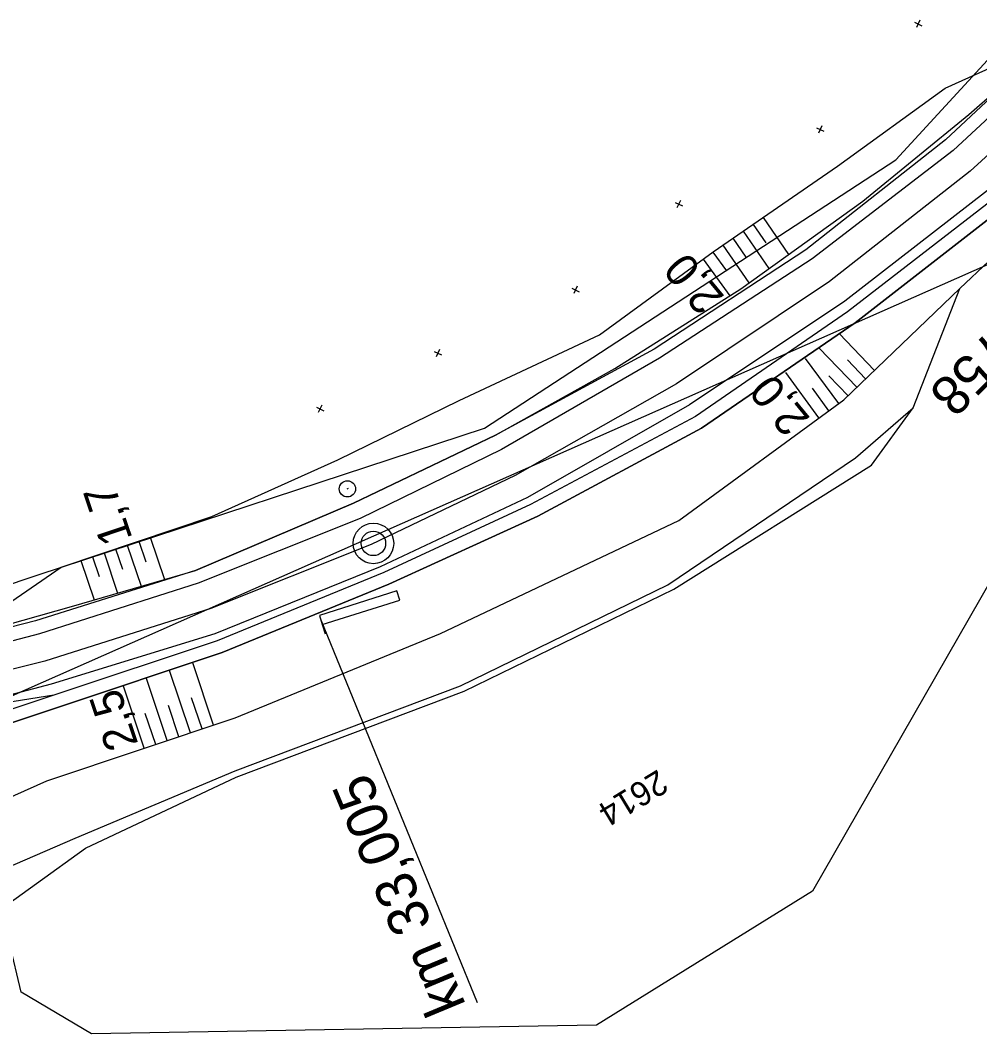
# Model space of a CAD drawing. Extents: x -804166 to -803706, y -1151030 to -1150147.
# Drawn here: x -803968.4 to -803909.4, y -1150743 to -1150680.7 of the extents above; entities that cross this region are included whole.
import ezdxf

# ---------------------------------------------------------------- set-up
doc = ezdxf.new("R2010")
doc.units = 0
for name, color, linetype in [('0381KM032-037P - Vrstva 1', 7, 'Continuous'), ('0381KM032-037P - Vrstva 13', 7, 'Continuous'), ('0381KM032-037P - Vrstva 4', 7, 'Continuous'), ('0381KM032-037P - Vrstva 48', 7, 'Continuous'), ('0381KM032-037P - Vrstva 49', 7, 'Continuous'), ('0381KM032-037P - Vrstva 57', 7, 'Continuous'), ('0381KM032-037P - Vrstva 7', 7, 'Continuous'), ('0381KM032-037P - Vrstva 9', 7, 'Continuous'), ('hran DP - hran DP', 7, 'Continuous'), ('vyt_sit - polygon', 7, 'Continuous'), ('vyt_sit - stávající', 7, 'Continuous')]:
    doc.layers.add(name, color=color, linetype=linetype)

msp = doc.modelspace()

# ---------------------------------------------------------------- linework, layer by layer
at = {"layer": '0381KM032-037P - Vrstva 1'}
msp.add_lwpolyline([(-803901.906, -1150682.605), (-803910.014, -1150690), (-803918.643, -1150696.775), (-803928.041, -1150703.062), (-803937.946, -1150708.688), (-803946.795, -1150712.932), (-803956.655, -1150716.869), (-803966.853, -1150720.098), (-803973.694, -1150721.813), (-803983.505, -1150723.682), (-803993.918, -1150724.91), (-804004.459, -1150725.421), (-804014.948, -1150725.206), (-804025.475, -1150724.252), (-804035.41, -1150722.673), (-804044.081, -1150720.735), (-804054.774, -1150717.615), (-804061.472, -1150715.138)], dxfattribs=at)
at = {"layer": '0381KM032-037P - Vrstva 13'}
for points in [[(-803902.54, -1150686.99), (-803908.533, -1150691.682), (-803917.537, -1150698.646), (-803926.885, -1150705.063), (-803937.003, -1150710.487), (-803946.017, -1150714.661), (-803956.263, -1150718.85), (-803966.288, -1150722.189), (-803972.538, -1150724.259)], [(-803972.286, -1150725.012), (-803966.125, -1150722.974), (-803955.955, -1150719.581), (-803945.709, -1150715.376), (-803936.565, -1150711.19), (-803926.506, -1150705.78), (-803917.073, -1150699.315), (-803908.044, -1150692.29), (-803902.092, -1150687.65)]]:
    msp.add_lwpolyline(points, dxfattribs=at)
at = {"layer": '0381KM032-037P - Vrstva 4'}
msp.add_line((-803966.288, -1150722.189), (-803973.383, -1150723.337), dxfattribs=at)
for points in [[(-803904.886, -1150683.001), (-803906.516, -1150683.391), (-803911.518, -1150688.069), (-803920.109, -1150694.835), (-803929.412, -1150700.935), (-803939.155, -1150706.209), (-803947.889, -1150710.398), (-803957.601, -1150714.533), (-803967.413, -1150717.637)], [(-803904.886, -1150683.001), (-803911.05, -1150688.735), (-803919.705, -1150695.384), (-803929.087, -1150701.477), (-803938.787, -1150707.105), (-803947.481, -1150711.337), (-803957.418, -1150715.321), (-803967.176, -1150718.433)], [(-803902.503, -1150685.469), (-803908.943, -1150691.185), (-803917.694, -1150697.991), (-803927.241, -1150704.348), (-803937.195, -1150710.055), (-803946.246, -1150714.302), (-803956.405, -1150718.419), (-803966.448, -1150721.526)], [(-803902.503, -1150685.469), (-803902.54, -1150686.99), (-803908.533, -1150691.682), (-803917.537, -1150698.646), (-803926.885, -1150705.063), (-803937.003, -1150710.487), (-803946.017, -1150714.661), (-803956.263, -1150718.85), (-803966.288, -1150722.189)], [(-803967.413, -1150717.637), (-803975.823, -1150719.769), (-803983.88, -1150721.36), (-803994.176, -1150722.403), (-804004.636, -1150722.95), (-804014.864, -1150722.688), (-804025.142, -1150721.989), (-804034.984, -1150720.624), (-804043.408, -1150718.773), (-804051.925, -1150716.215), (-804054.245, -1150715.484), (-804061.999, -1150712.588)], [(-803967.176, -1150718.433), (-803974.218, -1150720.269), (-803983.735, -1150722.132), (-803994.129, -1150723.262), (-804004.519, -1150723.869), (-804015.047, -1150723.539), (-804025.265, -1150722.781), (-804035.168, -1150721.131), (-804043.667, -1150719.322), (-804054.385, -1150716.187), (-804061.833, -1150713.392)], [(-803966.448, -1150721.526), (-803973.383, -1150723.337), (-803975.353, -1150723.792), (-803983.323, -1150725.373), (-803993.816, -1150726.434), (-804004.802, -1150726.955), (-804015.292, -1150726.922), (-804025.602, -1150725.763), (-804035.878, -1150724.109), (-804044.498, -1150722.129), (-804055.401, -1150719.075), (-804061.092, -1150716.98)]]:
    msp.add_lwpolyline(points, dxfattribs=at)
at = {"layer": '0381KM032-037P - Vrstva 48'}
for p, q in [((-803922.724, -1150692.839), (-803921.156, -1150695.111)), ((-803923.341, -1150693.265), (-803922.553, -1150694.407)), ((-803924.575, -1150694.118), (-803923.779, -1150695.271)), ((-803923.958, -1150693.691), (-803922.374, -1150695.987)), ((-803925.193, -1150694.544), (-803923.592, -1150696.863)), ((-803925.809, -1150694.97), (-803924.975, -1150696.112)), ((-803926.415, -1150695.413), (-803924.777, -1150697.655)), ((-803915.883, -1150702.24), (-803918.059, -1150699.974)), ((-803916.965, -1150703.279), (-803919.272, -1150700.876)), ((-803918.079, -1150704.279), (-803920.11, -1150701.499)), ((-803916.424, -1150702.759), (-803917.545, -1150701.592)), ((-803919.291, -1150705.163), (-803921.33, -1150702.372)), ((-803917.506, -1150703.798), (-803918.692, -1150702.563)), ((-803918.685, -1150704.721), (-803919.698, -1150703.334)), ((-803961.077, -1150712.73), (-803960.645, -1150714.011)), ((-803960.366, -1150712.49), (-803959.492, -1150715.083)), ((-803962.498, -1150713.21), (-803962.076, -1150714.461)), ((-803961.787, -1150712.97), (-803960.933, -1150715.502)), ((-803964.63, -1150713.929), (-803963.816, -1150716.341)), ((-803963.919, -1150713.689), (-803963.508, -1150714.91)), ((-803963.209, -1150713.449), (-803962.375, -1150715.921)), ((-803956.479, -1150724.031), (-803957.763, -1150720.201)), ((-803957.902, -1150724.508), (-803959.183, -1150720.684)), ((-803959.324, -1150724.985), (-803960.603, -1150721.167)), ((-803960.746, -1150725.461), (-803962.023, -1150721.65)), ((-803957.19, -1150724.27), (-803957.832, -1150722.356)), ((-803960.035, -1150725.223), (-803960.674, -1150723.316)), ((-803958.613, -1150724.746), (-803959.253, -1150722.836))]:
    msp.add_line(p, q, dxfattribs=at)
at = {"layer": '0381KM032-037P - Vrstva 49'}
for p, q in [((-803913.423, -1150680.841), (-803912.971, -1150681.057)), ((-803913.089, -1150680.723), (-803913.305, -1150681.175)), ((-803919.115, -1150687.214), (-803919.331, -1150687.666)), ((-803919.449, -1150687.332), (-803918.997, -1150687.548)), ((-803928.133, -1150691.918), (-803927.681, -1150692.134)), ((-803927.799, -1150691.8), (-803928.015, -1150692.252)), ((-803934.479, -1150697.185), (-803934.027, -1150697.401)), ((-803934.145, -1150697.067), (-803934.361, -1150697.519)), ((-803942.593, -1150700.952), (-803942.809, -1150701.404)), ((-803942.927, -1150701.07), (-803942.475, -1150701.286)), ((-803950.166, -1150704.501), (-803949.714, -1150704.717)), ((-803949.832, -1150704.383), (-803950.048, -1150704.835))]:
    msp.add_line(p, q, dxfattribs=at)
for points in [[(-803984.817, -1150721.442), (-803974.636, -1150719.233), (-803973.09, -1150718.927), (-803972.805, -1150718.807), (-803972.246, -1150718.741), (-803965.21, -1150716.746), (-803957.601, -1150714.533), (-803947.889, -1150710.398), (-803939.155, -1150706.209), (-803931.831, -1150702.119), (-803924.086, -1150697.218), (-803916.608, -1150691.841), (-803910.081, -1150686.51), (-803906.516, -1150683.391), (-803903.605, -1150681.318)], [(-803972.246, -1150718.741), (-803965.841, -1150714.337), (-803956.596, -1150711.219), (-803948.841, -1150707.727), (-803941.393, -1150704.085), (-803932.776, -1150700.061), (-803925.787, -1150694.954), (-803918.146, -1150689.679), (-803911.549, -1150684.903), (-803903.605, -1150681.318)], [(-803973.24, -1150730.36), (-803966.718, -1150727.463), (-803955.163, -1150723.59), (-803942.536, -1150718.416), (-803927.909, -1150711.458), (-803917.773, -1150704.055), (-803910.649, -1150697.212), (-803903.52, -1150690.487), (-803900.099, -1150686.57)], [(-803902.092, -1150687.65), (-803908.044, -1150692.29), (-803917.073, -1150699.315), (-803926.506, -1150705.78), (-803936.565, -1150711.19), (-803945.709, -1150715.376), (-803955.955, -1150719.581), (-803966.125, -1150722.974), (-803972.286, -1150725.012), (-803974.7, -1150725.768), (-803983.368, -1150727.37), (-803993.836, -1150727.905), (-804004.989, -1150728.615), (-804004.868, -1150729.928), (-804012.985, -1150730.258), (-804018.762, -1150729.808), (-804029.792, -1150728.642), (-804054.152, -1150723.147), (-804060.274, -1150720.943)], [(-803970.39, -1150735.93), (-803964.347, -1150731.606), (-803955.102, -1150727.225), (-803941.078, -1150721.948), (-803928.207, -1150715.68), (-803916.068, -1150708.06), (-803913.504, -1150704.534), (-803910.649, -1150697.212)], [(-803971.76, -1150733.922), (-803964.987, -1150730.973), (-803955.152, -1150726.847), (-803941.304, -1150721.616), (-803928.584, -1150715.413), (-803917.051, -1150707.621), (-803913.504, -1150704.534)]]:
    msp.add_lwpolyline(points, dxfattribs=at)
at = {"layer": '0381KM032-037P - Vrstva 7'}
msp.add_line((-803948.213, -1150709.499), (-803948.305, -1150709.537), dxfattribs=at)
for centre, radius in [((-803948.259, -1150709.518), 0.5), ((-803946.663, -1150712.869), 1.246), ((-803946.663, -1150712.869), 0.752)]:
    msp.add_circle(centre, radius, dxfattribs=at)
at = {"layer": '0381KM032-037P - Vrstva 9'}
for p, q in [((-803945.217, -1150715.777), (-803949.983, -1150717.29)), ((-803945.036, -1150716.348), (-803945.217, -1150715.777)), ((-803949.801, -1150717.862), (-803945.036, -1150716.348)), ((-803949.983, -1150717.29), (-803949.801, -1150717.862)), ((-803949.892, -1150717.576), (-803940.281, -1150741.083)), ((-803949.801, -1150717.862), (-803949.62, -1150718.434))]:
    msp.add_line(p, q, dxfattribs=at)
at = {"layer": 'hran DP - hran DP'}
for p, q in [((-803914.58, -1150689.29), (-803907.67, -1150681.78)), ((-803939.84, -1150705.78), (-803914.58, -1150689.29)), ((-803967.26, -1150714.81), (-803939.84, -1150705.78)), ((-803905.7, -1150709.82), (-803919.68, -1150734.23)), ((-803976.9, -1150717.98), (-803967.26, -1150714.81)), ((-803968.3, -1150740.45), (-803970.22, -1150732.49)), ((-803919.68, -1150734.23), (-803932.96, -1150742.47)), ((-803963.98, -1150743), (-803968.3, -1150740.45)), ((-803932.96, -1150742.47), (-803963.98, -1150743))]:
    msp.add_line(p, q, dxfattribs=at)
at = {"layer": 'vyt_sit - polygon'}
msp.add_line((-803975.818, -1150725.31), (-803907.43, -1150695.075), dxfattribs=at)

# ---------------------------------------------------------------- texts
at = {"layer": '0381KM032-037P - Vrstva 48'}
for s, rotation, p in [('2,0', 129.61944, (-803925.039, -1150697.72)), ('2,0', 129.42518, (-803919.779, -1150705.196)), ('1,7', 108.63737, (-803961.445, -1150712.571)), ('2,5', 108.45016, (-803961.097, -1150725.192))]:
    msp.add_text(s, height=2, rotation=rotation, dxfattribs=at).set_placement(p)
at = {"layer": '0381KM032-037P - Vrstva 57'}
msp.add_text('2614', height=1.5, rotation=211.19956, dxfattribs=at).set_placement((-803929.177, -1150726.725))
at = {"layer": '0381KM032-037P - Vrstva 9'}
msp.add_text('km 33,005', height=2.5, rotation=112.61933, dxfattribs=at).set_placement((-803940.96, -1150741.243))
at = {"layer": 'vyt_sit - stávající'}
msp.add_text('ŽP 758', height=2.4, rotation=225, dxfattribs=at).set_placement((-803905.333, -1150696.219))

doc.saveas('drawing.dxf')
